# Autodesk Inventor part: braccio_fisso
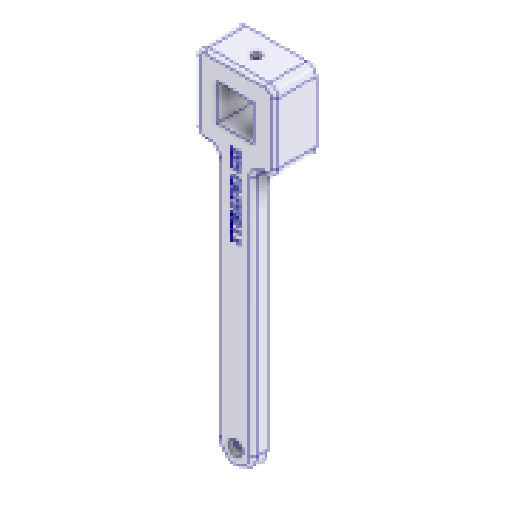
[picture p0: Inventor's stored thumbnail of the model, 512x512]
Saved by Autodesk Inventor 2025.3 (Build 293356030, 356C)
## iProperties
Created: 2025-09
Part Number: braccio_fisso
Material: Plastica PET
Document SubType Name: Modeling
Designer: Ryzen5700u
Density: 1.541 g/cm^3
Appearance: Bianco freddo
Mass: 89.885 g
Surface Area: 163.953 cm^2
Volume: 58.329 cm^3
Author: Ryzen5700u
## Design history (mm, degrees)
sketch "Schizzo1"
  geometry: L1 (-10.1, -10.1)-(10.1, -10.1); L2 (10.1, -10.1)-(10.1, 10.1); L3 (10.1, 10.1)-(-10.1, 10.1); L4 (-10.1, 10.1)-(-10.1, -10.1); L5 (-10.1, -10.1)-(10.1, 10.1); L6 (10.1, -10.1)-(-10.1, 10.1); L7 (-22, -22)-(22, -22); L8 (22, -22)-(22, 22); L9 (22, 22)-(-22, 22); L10 (-22, 22)-(-22, -22); L11 (-22, -22)-(22, 22); L12 (22, -22)-(-22, 22); L13 (-10, -22)-(10, -22); L14 (10, -22)-(10, -172); L15 (10, -172)-(-10, -172); L16 (-10, -172)-(-10, -22); 2 further points
  constraints: 32 end point, 6 parallel, 4 midpoint, 3 horizontal, 3 perpendicular, 1 point on line
  dimensions: "d0" = 20.2 distance of L3.end L2.end; "d1" = 20.2 distance of L2.end L1.end; "d2" = 44 distance of L9.end L8.end; "d3" = 44 distance of L7.end L8.end; "d4" = 150 distance of L13.end L14.end
extrude "Estrusione1" new body sketch "Schizzo1" distance "d5" = 8; taper "d6" = 0 deg
sketch "Schizzo2"
  geometry: L1 (22, -22)-(10, -22) reference; L2 (22, 22)-(22, -22) reference; L3 (-22, 22)-(22, 22) reference; L4 (-22, -22)-(-22, 22) reference; L5 (-10, -22)-(-22, -22) reference; L6 (-10, -172)-(-10, -22) reference; L7 (10, -172)-(-10, -172) reference; L8 (10, -22)-(10, -172) reference; L9 (10.1, -10.1)-(10.1, 10.1) reference; L10 (-10.1, -10.1)-(10.1, -10.1) reference; L11 (-10.1, 10.1)-(-10.1, -10.1) reference; L12 (10.1, 10.1)-(-10.1, 10.1) reference; L13 (10, -22)-(-10, -22); 1 further point
  constraints: 2 end point, 1 horizontal
extrude "Estrusione2" join sketch "Schizzo2" distance "d7" = 15; taper "d8" = 0 deg
sketch "Schizzo3"
  geometry: L1 (44, 23)-(44, 0) reference; L2 (44, 23)-(0, 23) reference; L3 (44, 0)-(0, 23); L4 (0, 0)-(0, 23) reference; L5 (0, 23)-(0, 0); L6 (0, 0)-(45.029, 22.647); 2 further points
  constraints: 6 end point, 2 point on line, 1 collinear
hole "Foro1" sketch "Schizzo3" at (22.424, 11.278) diameter "d9" = 5.3; stored, may be unused: countersink angle "d13" = 90 deg, drill point angle "d15" = 118 deg; dims "d10" = 6, "d11" = 10, "d12" = 5.7, "d14" = 64.25
fillet "Raccordo1" dims "d16" = 5
sketch "Schizzo6"
  geometry: L1 (2.697, -16.966)-(2.697, -70.179); L2 (2.697, -70.179)-(-3.392, -70.179); L3 (-3.392, -70.179)-(-3.392, -16.966); L4 (-3.392, -16.966)-(2.697, -16.966); 1 further point
  constraints: 2 other
extrude "Estrusione5" cut sketch "Schizzo6" distance "d23" = 0.2; taper "d24" = 0 deg
fillet "Raccordo3" dims "d25" = 15
fillet "Raccordo6" dims "d28" = 10
sketch "Schizzo7"
  geometry: L1 (10, -162)-(10, -27) reference; L2 (15, -22)-(17, -22) reference; L3 (22, -17)-(22, 17) reference; L4 (17, 22)-(-17, 22) reference; L5 (-22, 17)-(-22, -17) reference; L6 (-17, -22)-(-15, -22) reference; L7 (-10, -27)-(-10, -162) reference; L8 (-1.448, -59.863)-(-2.4, -59.863) reference; L9 (-2.4, -59.863)-(-2.4, -56.528) reference; L10 (-2.4, -56.528)-(2.6, -56.528) reference; L11 (2.6, -56.528)-(2.6, -57.784) reference; L12 (2.6, -57.784)-(-1.448, -57.784) reference; L13 (-1.448, -57.784)-(-1.448, -59.863) reference; L14 (-2.4, -51.743)-(-2.4, -48.364) reference; L15 (-2.4, -48.364)-(2.6, -48.364) reference; L16 (2.6, -48.364)-(2.6, -51.743) reference; L17 (2.6, -51.743)-(1.647, -51.743) reference; L18 (1.647, -51.743)-(1.647, -49.612) reference; L19 (1.647, -49.612)-(0.768, -49.612) reference; L20 (0.768, -49.612)-(0.768, -51.577) reference; L21 (0.768, -51.577)-(-0.184, -51.577) reference; L22 (-0.184, -51.577)-(-0.184, -49.612) reference; L23 (-0.184, -49.612)-(-1.448, -49.612) reference; L24 (-1.448, -49.612)-(-1.448, -51.743) reference; L25 (-1.448, -51.743)-(-2.4, -51.743) reference; L26 (-2.105, -39.527)-(-0.913, -39.527) reference; L27 (-0.913, -39.527)-(-0.913, -39.64) reference; L28 (2.352, -43.311)-(1.21, -43.311) reference; L29 (1.21, -43.311)-(1.21, -43.202) reference; L30 (-2.4, -35.807)-(-2.4, -34.551) reference; L31 (-2.4, -34.551)-(2.6, -36.241) reference; L32 (2.6, -36.241)-(2.6, -37.61) reference; L33 (2.6, -37.61)-(-2.4, -39.3) reference; L34 (-2.4, -39.3)-(-2.4, -38.007) reference; L35 (-2.4, -38.007)-(-1.379, -37.695) reference; L36 (-1.379, -37.695)-(-1.379, -36.123) reference; L37 (-1.379, -36.123)-(-2.4, -35.807) reference; L38 (-2.105, -23.858)-(-0.913, -23.858) reference; L39 (-0.913, -23.858)-(-0.913, -23.972) reference; L40 (2.352, -27.643)-(1.21, -27.643) reference; L41 (1.21, -27.643)-(1.21, -27.533) reference; L42 (-1.529, -19.972)-(-2.4, -19.972) reference; L43 (-2.4, -19.972)-(-2.4, -17.282) reference; L44 (-2.4, -17.282)-(-1.529, -17.282) reference; L45 (-1.529, -17.282)-(-1.529, -17.999) reference; L46 (-1.529, -17.999)-(1.728, -17.999) reference; L47 (1.728, -17.999)-(1.728, -17.282) reference; L48 (1.728, -17.282)-(2.6, -17.282) reference; L49 (2.6, -17.282)-(2.6, -19.972) reference; L50 (2.6, -19.972)-(1.728, -19.972) reference; L51 (1.728, -19.972)-(1.728, -19.255) reference; L52 (1.728, -19.255)-(-1.529, -19.255) reference; L53 (-1.529, -19.255)-(-1.529, -19.972) reference; L54 (-1.529, -23.295)-(-2.4, -23.295) reference; L55 (-2.4, -23.295)-(-2.4, -20.604) reference; L56 (-2.4, -20.604)-(-1.529, -20.604) reference; L57 (-1.529, -20.604)-(-1.529, -21.322) reference; L58 (-1.529, -21.322)-(1.728, -21.322) reference; L59 (1.728, -21.322)-(1.728, -20.604) reference; L60 (1.728, -20.604)-(2.6, -20.604) reference; L61 (2.6, -20.604)-(2.6, -23.295) reference; L62 (2.6, -23.295)-(1.728, -23.295) reference; L63 (1.728, -23.295)-(1.728, -22.578) reference; L64 (1.728, -22.578)-(-1.529, -22.578) reference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; C1 r 15 at (0, -162); A1 r 10 centre (0, -162) between (-10, -162) and (10, -162) reference; A2 r 10 centre (0, -162) between (-10, -162) and (10, -162) reference; A3 r 5 centre (15, -27) between (15, -22) and (10, -27) reference; A4 r 5 centre (17, -17) between (17, -22) and (22, -17) reference; A5 r 5 centre (17, 17) between (22, 17) and (17, 22) reference; A6 r 5 centre (-17, 17) between (-17, 22) and (-22, 17) reference; A7 r 5 centre (-17, -17) between (-22, -17) and (-17, -22) reference; A8 r 5 centre (-15, -27) between (-10, -27) and (-15, -22) reference; 45 further points
  constraints: 1 centre point, 1 coincident, 46 other
  dimensions: "d29" = 30 diameter of C1
extrude "Estrusione6" join sketch "Schizzo7" stored distance "d30" = 10; taper "d31" = 0 deg
sketch "Schizzo8"
  geometry: A1 r 10 centre (0, -162) between (-10, -162) and (10, -162) reference; 4 further points
  constraints: 1 coincident
hole "Foro2" sketch "Schizzo8" at (0, -162) diameter "d32" = 4.5; stored, may be unused: countersink angle "d36" = 90 deg, drill point angle "d38" = 118 deg; dims "d33" = 6, "d34" = 8, "d35" = 4.6, "d37" = 8
sketch "Schizzo9"
  geometry: L1 (4.5, -162)-(2.25, -165.897); L2 (2.25, -165.897)-(-2.25, -165.897); L3 (-2.25, -165.897)-(-4.5, -162); L4 (-4.5, -162)-(-2.25, -158.103); L5 (-2.25, -158.103)-(2.25, -158.103); L6 (2.25, -158.103)-(4.5, -162); C1 r 2.25 at (0, -162) reference; 2 further points
  constraints: 12 end point, 1 coincident, 13 other
  dimensions: "d39" = 4.5 distance of L1.end L2.end
extrude "Estrusione7" cut sketch "Schizzo9" distance "d40" = 3; taper "d41" = 0 deg
fillet "Raccordo7" dims "d42" = 2
fillet "Raccordo8" dims "d43" = 2
sketch "Schizzo10"
  geometry: C1 r 2.25 at (0, -162) reference; 2 further points
  constraints: 1 coincident
hole "Foro3" sketch "Schizzo10" at (0, -162) diameter "d44" = 4.5; stored, may be unused: countersink angle "d48" = 90 deg, drill point angle "d50" = 118 deg; dims "d45" = 6, "d46" = 8, "d47" = 3.4, "d49" = 8
fillet "Raccordo9" dims "d51" = 2
node "Solido1"
node "Linea chiusa proiettata1"
node "Linea chiusa proiettata2"
